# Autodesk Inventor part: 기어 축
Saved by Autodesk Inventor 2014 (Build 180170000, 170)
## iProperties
Created: 2026-04
Part Number: 기어 축
Material: 강철, 합금
Document SubType Name: Modeling
Designer: dg
Density: 7.85 g/cm^3
Appearance: 반연마
Mass: 284.982 g
Surface Area: 98.4336 cm^2
Volume: 36.3034 cm^3
Author: jhkim
Creation Date: 2026-03-27
Sending System: Autodesk Inventor 2026
Preprocessor: ST-DEVELOPER v20.1
Author: dg
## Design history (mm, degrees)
node "기어 축1"
node "솔리드1"
node "기준1"
